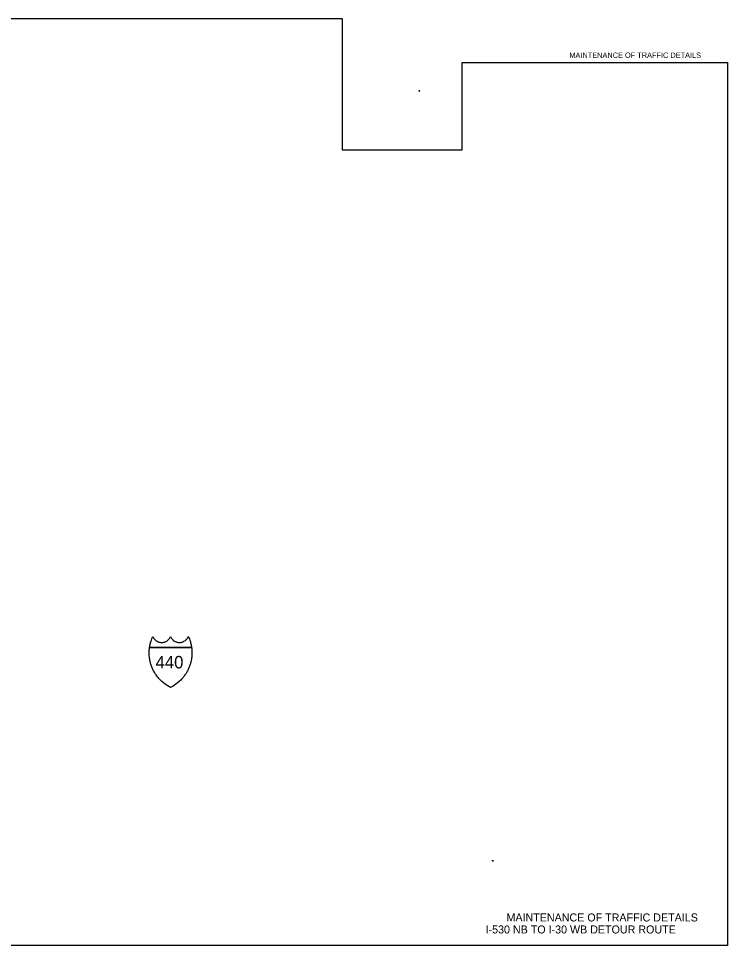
# Model space of a CAD drawing. Extents: x 759117 to 1215197, y 961017 to 2072683.
# Drawn here: x 838885 to 918653, y 961017 to 1065249 of the extents above; entities that cross this region are included whole.
import ezdxf

# ---------------------------------------------------------------- set-up
doc = ezdxf.new("R2010")
doc.units = 0
for name, color, linetype in [('23', 7, 'Continuous'), ('G-ANNO-TEXT', 7, 'Continuous'), ('NO PLOT CELL', 7, 'Continuous')]:
    doc.layers.add(name, color=color, linetype=linetype)

msp = doc.modelspace()

# ---------------------------------------------------------------- linework, layer by layer
at = {"layer": '23'}
for points in [[(853626, 994520), (853643, 994633), (853661, 994733), (853687, 994862), (853707, 994946), (853732, 995045), (853765, 995163), (853795, 995261), (853829, 995362), (853874, 995486), (853921, 995602), (853959, 995693), (853991, 995764), (854026, 995687), (854066, 995614), (854111, 995547), (854168, 995472), (854214, 995422), (854270, 995367), (854327, 995320), (854389, 995275), (854487, 995216), (854587, 995169), (854679, 995137), (854769, 995114), (854865, 995098), (854978, 995090), (855051, 995092), (855136, 995100), (855212, 995113), (855292, 995132), (855374, 995159), (855483, 995208), (855559, 995250), (855646, 995310), (855731, 995381), (855792, 995443), (855862, 995528), (855920, 995614), (855954, 995675), (855991, 995755)], [(855991, 995755), (856028, 995675), (856062, 995614), (856120, 995528), (856190, 995443), (856252, 995381), (856336, 995310), (856423, 995250), (856499, 995208), (856608, 995159), (856690, 995132), (856771, 995113), (856846, 995100), (856931, 995092), (857005, 995090), (857117, 995098), (857214, 995114), (857304, 995137), (857395, 995169), (857495, 995216), (857594, 995275), (857655, 995320), (857712, 995367), (857769, 995422), (857814, 995472), (857872, 995547), (857916, 995614), (857956, 995687), (857991, 995764), (858023, 995693), (858062, 995602), (858108, 995486), (858153, 995362), (858187, 995261), (858217, 995163), (858250, 995045), (858275, 994946), (858295, 994862), (858321, 994733), (858339, 994633), (858357, 994520)], [(855991, 990038), (855784, 990149), (855601, 990259), (855401, 990394), (855214, 990536), (855009, 990710), (854932, 990781), (854846, 990867), (854765, 990950), (854677, 991046), (854590, 991147), (854518, 991236), (854440, 991338), (854369, 991436), (854307, 991527), (854253, 991610), (854208, 991682), (854149, 991783), (854103, 991866), (854052, 991963), (854003, 992063), (853960, 992155), (853921, 992245), (853881, 992345), (853845, 992438), (853811, 992535), (853778, 992636), (853747, 992739), (853720, 992838), (853696, 992932), (853677, 993016), (853664, 993078), (853642, 993199), (853620, 993338), (853605, 993454), (853595, 993576), (853588, 993675), (853584, 993800), (853583, 993917), (853585, 994047), (853589, 994133), (853593, 994211), (853597, 994261), (853609, 994389), (853626, 994520)], [(858357, 994520), (853626, 994520)], [(853626, 994520), (858357, 994520)], [(858357, 994520), (858373, 994389), (858385, 994261), (858389, 994211), (858394, 994133), (858397, 994047), (858400, 993917), (858398, 993800), (858394, 993675), (858388, 993576), (858377, 993454), (858362, 993338), (858341, 993199), (858318, 993078), (858305, 993016), (858286, 992932), (858263, 992838), (858235, 992739), (858204, 992636), (858171, 992535), (858137, 992438), (858102, 992345), (858061, 992245), (858022, 992155), (857979, 992063), (857930, 991963), (857879, 991866), (857833, 991783), (857774, 991682), (857729, 991610), (857675, 991527), (857613, 991436), (857542, 991338), (857464, 991236), (857392, 991147), (857305, 991046), (857217, 990950), (857137, 990867), (857050, 990781), (856973, 990710), (856769, 990536), (856581, 990394), (856381, 990259), (856198, 990149), (855991, 990038)]]:
    msp.add_lwpolyline(points, dxfattribs=at)
at = {"layer": 'NO PLOT CELL'}
msp.add_lwpolyline([(875318, 1065249), (875318, 1050499), (888818, 1050499), (888818, 1060294), (918653, 1060294), (918653, 1045544), (918653, 961017), (759117, 961017), (759117, 1065249)], close=True, dxfattribs=at)
for centre in [(883983, 1057123), (892247, 970529)]:
    msp.add_circle(centre, 50, dxfattribs=at)

# ---------------------------------------------------------------- texts
at = {"layer": 'G-ANNO-TEXT'}
for s, height, p in [('MAINTENANCE OF TRAFFIC DETAILS', 600, (900861, 1060828)), ('440', 1402.1, (854306, 992171)), ('MAINTENANCE OF TRAFFIC DETAILS', 900, (893790, 963717)), ('I-530 NB TO I-30 WB DETOUR ROUTE', 900, (891437, 962367))]:
    msp.add_text(s, height=height, dxfattribs=at).set_placement(p)

doc.saveas('drawing.dxf')
